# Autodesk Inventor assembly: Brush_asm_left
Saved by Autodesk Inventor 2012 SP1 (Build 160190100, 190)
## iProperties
Created: 2006-04
Part Number: Brush_asm_left
Document SubType Name: Assembly
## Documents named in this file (4)
- D:\Backup\Autodesk Motion Files\Inv2012DynSim\Sub-Assemblies\Brush_asm_left.iam
- D:\Backup\Autodesk Motion Files\Inv2012DynSim\Parts\Arm.ipt
- D:\Backup\Autodesk Motion Files\Inv2012DynSim\Parts\Wiper.ipt
- D:\Backup\Autodesk Motion Files\Inv2012DynSim\Parts\Brush.ipt
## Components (3 placed, 3 different names)
1. Arm:1
2. Wiper:1
3. Brush:1
